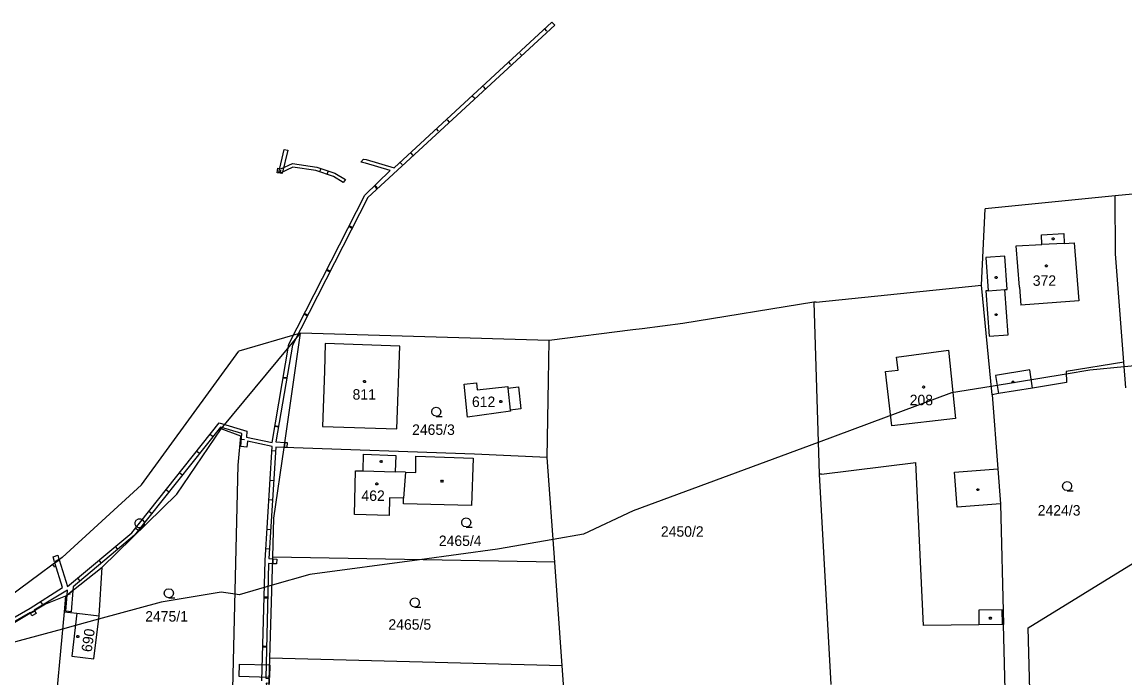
# Model space of a CAD drawing. Extents: x -760611 to -758411, y -1176479 to -1174807.
# Drawn here: x -759156.8 to -758977.4, y -1175029.4 to -1174922.6 of the extents above; entities that cross this region are included whole.
import ezdxf

# ---------------------------------------------------------------- set-up
doc = ezdxf.new("R2010")
doc.units = 0
for name, color, linetype in [('1', 7, 'Continuous'), ('11', 7, 'Continuous'), ('12', 7, 'Continuous'), ('13', 7, 'Continuous'), ('2', 7, 'Continuous'), ('3', 7, 'Continuous'), ('4', 7, 'Continuous'), ('5', 7, 'Continuous'), ('8', 7, 'Continuous')]:
    doc.layers.add(name, color=color, linetype=linetype)

msp = doc.modelspace()

# ---------------------------------------------------------------- linework, layer by layer
at = {"layer": '1'}
for p, q in [((-758953.71, -1174948.54), (-758979.01, -1174950.9)), ((-758979.01, -1174950.9), (-759000.12, -1174953.04)), ((-758978.92, -1174960.34), (-758979.01, -1174950.9)), ((-759000.75, -1174965.43), (-759000.12, -1174953.04)), ((-758977.57, -1174977.98), (-758978.92, -1174960.34)), ((-759027.66, -1174968.22), (-759000.75, -1174965.43)), ((-758999.02, -1174983.26), (-759000.75, -1174965.43)), ((-759028.01, -1174968.19), (-759049.31, -1174971.65)), ((-759028.01, -1174968.19), (-759027.14, -1174996.19)), ((-759027.66, -1174968.22), (-759028.01, -1174968.19)), ((-759049.31, -1174971.65), (-759055.94, -1174972.53)), ((-759124.45, -1174988.84), (-759111.53, -1174973.24)), ((-759111.53, -1174973.24), (-759121.55, -1174976.17)), ((-759114.2, -1174991.84), (-759111.53, -1174973.24)), ((-759071.06, -1174974.46), (-759111.53, -1174973.24)), ((-759057.44, -1174972.72), (-759071.06, -1174974.46)), ((-759055.94, -1174972.53), (-759057.44, -1174972.72)), ((-759107.51, -1174974.94), (-759107.61, -1174979.42)), ((-759095.35, -1174975.38), (-759107.51, -1174974.94)), ((-759095.86, -1174988.83), (-759095.35, -1174975.38)), ((-759071.18, -1174980.94), (-759071.06, -1174974.46)), ((-759137.42, -1174997.94), (-759121.55, -1174976.17)), ((-758977.57, -1174977.98), (-758986.97, -1174979.5)), ((-758977.24, -1174982.16), (-758977.57, -1174977.98)), ((-759107.61, -1174979.42), (-759107.95, -1174988.44)), ((-759071.42, -1174993.47), (-759071.18, -1174980.94)), ((-758986.97, -1174979.5), (-758986.89, -1174981.3)), ((-759084.91, -1174981.56), (-759082.9, -1174981.34)), ((-759084.36, -1174986.93), (-759084.91, -1174981.56)), ((-759082.9, -1174981.34), (-759082.77, -1174982.45)), ((-759082.77, -1174982.45), (-759077.83, -1174981.91)), ((-759077.83, -1174981.91), (-759077.8, -1174982.17)), ((-759077.8, -1174982.17), (-759076.06, -1174981.98)), ((-759076.06, -1174981.98), (-759075.68, -1174985.56)), ((-758992.42, -1174982.19), (-758998, -1174983.09)), ((-758986.89, -1174981.3), (-758992.42, -1174982.19)), ((-758998, -1174983.09), (-758999.02, -1174983.26)), ((-758999.02, -1174983.26), (-758998.09, -1174995.31)), ((-759077.38, -1174985.96), (-759084.36, -1174986.93)), ((-759075.68, -1174985.56), (-759077.41, -1174985.75)), ((-759077.41, -1174985.75), (-759077.38, -1174985.96)), ((-759131.66, -1174999.44), (-759124.45, -1174988.84)), ((-759121.24, -1174989.98), (-759124.45, -1174988.84)), ((-759121.67, -1174994.74), (-759121.24, -1174989.98)), ((-759107.95, -1174988.44), (-759095.86, -1174988.83)), ((-759115.85, -1175003.37), (-759114.2, -1174991.84)), ((-759083.21, -1174992.95), (-759114.2, -1174991.84)), ((-759101.36, -1174995.63), (-759101.27, -1174992.95)), ((-759101.27, -1174992.95), (-759096.01, -1174993.14)), ((-759096.01, -1174993.14), (-759096.11, -1174995.82)), ((-759092.75, -1174995.94), (-759092.75, -1174993.25)), ((-759092.75, -1174993.25), (-759083.45, -1174993.6)), ((-759083.45, -1174993.6), (-759083.74, -1175001.31)), ((-759071.42, -1174993.47), (-759083.21, -1174992.95)), ((-759070.18, -1175010.51), (-759071.42, -1174993.47)), ((-759122.62, -1175034.09), (-759121.67, -1174994.74)), ((-759026.79, -1174996.18), (-759011.4, -1174994.3)), ((-759010.16, -1175020.83), (-759011.4, -1174994.3)), ((-758998.09, -1174995.31), (-758997.64, -1175001)), ((-759102.77, -1175002.76), (-759102.56, -1174995.65)), ((-759102.56, -1174995.65), (-759101.36, -1174995.63)), ((-759094.47, -1174995.88), (-759096.11, -1174995.82)), ((-759094.47, -1174995.88), (-759092.75, -1174995.94)), ((-759026.79, -1174996.18), (-759027.14, -1174996.19)), ((-759027.14, -1174996.19), (-759025.28, -1175030.41)), ((-759150.3, -1175009.76), (-759137.42, -1174997.94)), ((-759143.8, -1175011.35), (-759131.66, -1174999.44)), ((-759097.05, -1175000.04), (-759097.13, -1175002.94)), ((-759094.76, -1175000.08), (-759097.05, -1175000.04)), ((-759094.78, -1175001), (-759094.76, -1175000.08)), ((-759083.74, -1175001.31), (-759094.78, -1175001)), ((-758997.64, -1175001), (-758997.14, -1175020.68)), ((-759116.03, -1175009.67), (-759115.85, -1175003.37)), ((-759097.13, -1175002.94), (-759102.77, -1175002.76)), ((-759150.3, -1175009.76), (-759164.6, -1175020.29)), ((-759116.51, -1175026.13), (-759116.03, -1175009.67)), ((-759070.18, -1175010.51), (-759116.03, -1175009.67)), ((-759149.75, -1175016.04), (-759143.8, -1175011.35)), ((-759144.31, -1175019.22), (-759143.8, -1175011.35)), ((-759068.96, -1175027.38), (-759070.18, -1175010.51)), ((-758993.13, -1175021.18), (-758975.38, -1175010.24)), ((-759149.75, -1175016.04), (-759153.04, -1175017.37)), ((-759149.75, -1175016.04), (-759149.99, -1175018.59)), ((-759153.04, -1175017.37), (-759165.84, -1175024.98)), ((-759149.99, -1175018.59), (-759151.16, -1175031.39)), ((-759149.99, -1175018.59), (-759147.92, -1175018.82)), ((-759147.92, -1175018.82), (-759148.74, -1175025.83)), ((-759145.14, -1175026.24), (-759144.31, -1175019.22)), ((-758997.35, -1175020.68), (-759001.17, -1175020.73)), ((-758997.14, -1175020.68), (-758997.35, -1175020.68)), ((-758995.64, -1175078.53), (-758997.14, -1175020.68)), ((-759001.17, -1175020.73), (-759010.16, -1175020.83)), ((-758991.77, -1175073.34), (-758993.13, -1175021.18)), ((-759148.74, -1175025.83), (-759145.14, -1175026.24)), ((-759116.98, -1175042.31), (-759116.51, -1175026.13)), ((-759068.96, -1175027.38), (-759116.51, -1175026.13)), ((-759067.85, -1175043.58), (-759068.96, -1175027.38))]:
    msp.add_line(p, q, dxfattribs=at)
at = {"layer": '11'}
msp.add_lwpolyline([(-758949.2, -1174976.06), (-758977.51, -1174978.74), (-758983.13, -1174979.27), (-758986.95, -1174979.9), (-758999.15, -1174981.9), (-759005.62, -1174982.97), (-759027.3, -1174991.01), (-759057.42, -1175002.17), (-759065.49, -1175005.94), (-759070.45, -1175006.82), (-759079.49, -1175008.41), (-759092.2, -1175010.11), (-759110.03, -1175012.49), (-759116.16, -1175014.27), (-759121.49, -1175015.82), (-759122.18, -1175015.72), (-759124.46, -1175015.38), (-759134.22, -1175017.02), (-759144.38, -1175019.8), (-759148.15, -1175020.83), (-759150.25, -1175021.4), (-759160.11, -1175024.09)], dxfattribs=at)
at = {"layer": '12'}
for p, q in [((-758995.08, -1174959.03), (-758990.91, -1174958.81)), ((-758994.57, -1174965.78), (-758995.08, -1174959.03)), ((-758987.29, -1174958.63), (-758990.91, -1174958.81)), ((-758987.29, -1174958.63), (-758985.65, -1174958.54)), ((-758985.65, -1174958.54), (-758984.89, -1174968)), ((-758994.57, -1174965.78), (-758994.35, -1174968.69)), ((-758984.89, -1174968), (-758994.35, -1174968.69)), ((-759107.51, -1174974.94), (-759107.61, -1174979.42)), ((-759095.35, -1174975.38), (-759107.51, -1174974.94)), ((-759095.86, -1174988.83), (-759095.35, -1174975.38)), ((-759014.55, -1174977.17), (-759006.11, -1174975.99)), ((-759014.31, -1174979.24), (-759014.55, -1174977.17)), ((-759006.11, -1174975.99), (-759004.99, -1174987.14)), ((-759016.36, -1174979.48), (-759014.31, -1174979.24)), ((-759107.61, -1174979.42), (-759107.95, -1174988.44)), ((-759015.32, -1174988.35), (-759016.36, -1174979.48)), ((-759084.91, -1174981.56), (-759082.9, -1174981.34)), ((-759084.36, -1174986.93), (-759084.91, -1174981.56)), ((-759082.9, -1174981.34), (-759082.77, -1174982.45)), ((-759082.77, -1174982.45), (-759077.83, -1174981.91)), ((-759077.83, -1174981.91), (-759077.8, -1174982.17)), ((-759077.8, -1174982.17), (-759077.41, -1174985.75)), ((-759077.38, -1174985.96), (-759084.36, -1174986.93)), ((-759077.41, -1174985.75), (-759077.38, -1174985.96)), ((-759004.99, -1174987.14), (-759015.32, -1174988.35)), ((-759107.95, -1174988.44), (-759095.86, -1174988.83)), ((-759102.77, -1175002.76), (-759102.56, -1174995.65)), ((-759102.56, -1174995.65), (-759101.36, -1174995.63)), ((-759101.36, -1174995.63), (-759096.11, -1174995.82)), ((-759094.47, -1174995.88), (-759096.11, -1174995.82)), ((-759094.47, -1174995.88), (-759094.76, -1175000.08)), ((-759097.05, -1175000.04), (-759097.13, -1175002.94)), ((-759094.76, -1175000.08), (-759097.05, -1175000.04)), ((-759097.13, -1175002.94), (-759102.77, -1175002.76)), ((-759147.92, -1175018.82), (-759148.74, -1175025.83)), ((-759147.92, -1175018.82), (-759144.31, -1175019.22)), ((-759145.14, -1175026.24), (-759144.31, -1175019.22)), ((-759148.74, -1175025.83), (-759145.14, -1175026.24))]:
    msp.add_line(p, q, dxfattribs=at)
at = {"layer": '13'}
for p, q in [((-759071.83, -1174923.74), (-759071.49, -1174924.1)), ((-759077.7, -1174929.17), (-759077.36, -1174929.53)), ((-759075.52, -1174928.08), (-759075.86, -1174927.72)), ((-759081.41, -1174933.5), (-759081.75, -1174933.13)), ((-759083.58, -1174934.6), (-759083.24, -1174934.96)), ((-759087.29, -1174938.92), (-759087.63, -1174938.55)), ((-759089.46, -1174940.02), (-759089.12, -1174940.39)), ((-759114.17, -1174943.38), (-759113.59, -1174943.48)), ((-759093.18, -1174944.34), (-759093.52, -1174943.97)), ((-759114.84, -1174947.23), (-759114.74, -1174946.74)), ((-759108.23, -1174946.43), (-759108.38, -1174946.91)), ((-759107.2, -1174947.4), (-759107.04, -1174946.93)), ((-759095.33, -1174945.45), (-759094.99, -1174945.82)), ((-759099.43, -1174949.18), (-759099.08, -1174949.54)), ((-759099.06, -1174949.76), (-759099.4, -1174949.39)), ((-759100.58, -1174951.15), (-759112.85, -1174975.22)), ((-759103.67, -1174955.86), (-759103.22, -1174956.09)), ((-759103.08, -1174956.05), (-759103.52, -1174955.82)), ((-759107.3, -1174962.99), (-759106.86, -1174963.22)), ((-759106.71, -1174963.18), (-759107.16, -1174962.95)), ((-759110.93, -1174970.12), (-759110.49, -1174970.35)), ((-759110.34, -1174970.3), (-759110.79, -1174970.08)), ((-759114.35, -1174980.4), (-759113.86, -1174980.48)), ((-759113.78, -1174980.64), (-759114.27, -1174980.56)), ((-759115.7, -1174988.29), (-759115.2, -1174988.37)), ((-759126.22, -1174989.69), (-759125.83, -1174990)), ((-759121.06, -1174989.59), (-759124.53, -1174988.55)), ((-759115.13, -1174988.53), (-759115.63, -1174988.44)), ((-759121.14, -1174990.48), (-759120.65, -1174990.53)), ((-759127.96, -1174992.85), (-759128.35, -1174992.54)), ((-759116.18, -1174992.34), (-759115.68, -1174992.37)), ((-759131.2, -1174995.95), (-759130.81, -1174996.26)), ((-759115.89, -1174997.27), (-759116.39, -1174997.24)), ((-759132.94, -1174999.11), (-759133.33, -1174998.8)), ((-759116.68, -1175000.33), (-759116.19, -1175000.36)), ((-759136.19, -1175002.21), (-759135.8, -1175002.52)), ((-759137.93, -1175005.36), (-759138.32, -1175005.05)), ((-759116.39, -1175005.25), (-759116.89, -1175005.22)), ((-759141.68, -1175007.97), (-759141.36, -1175008.35)), ((-759117.19, -1175008.31), (-759116.69, -1175008.34)), ((-759151.86, -1175010.91), (-759151.56, -1175011.31)), ((-759143.91, -1175010.65), (-759144.23, -1175010.27)), ((-759147.81, -1175013.11), (-759147.49, -1175013.49)), ((-759153.82, -1175016.94), (-759153.55, -1175017.36)), ((-759149.51, -1175015.68), (-759149.01, -1175015.72)), ((-759117.46, -1175016.3), (-759116.96, -1175016.32)), ((-759116.86, -1175016.21), (-759117.36, -1175016.2)), ((-759117.06, -1175024.21), (-759117.56, -1175024.19)), ((-759117.66, -1175024.3), (-759117.16, -1175024.31)), ((-759121.51, -1175029.13), (-759121.45, -1175027.09)), ((-759121.45, -1175027.09), (-759116.54, -1175027.23)), ((-759116.54, -1175027.23), (-759116.6, -1175029.27)), ((-759116.6, -1175029.27), (-759121.51, -1175029.13))]:
    msp.add_line(p, q, dxfattribs=at)
for points in [[(-759100.94, -1174945.57), (-759101.73, -1174945.44), (-759101.27, -1174944.91), (-759100.84, -1174944.98), (-759096.3, -1174946.35), (-759070.62, -1174922.62)], [(-759070.62, -1174922.62), (-759070.15, -1174923.14), (-759100.58, -1174951.15)], [(-759113.59, -1174943.48), (-759114.5, -1174947.24), (-759115.08, -1174947.1), (-759114.17, -1174943.38)], [(-759113.43, -1174975.02), (-759101.08, -1174950.78), (-759096.96, -1174946.79), (-759100.94, -1174945.57)], [(-759120.27, -1174989.2), (-759120.31, -1174990.16), (-759116.17, -1174991.05), (-759113.43, -1174975.02)], [(-759112.85, -1174975.22), (-759115.55, -1174990.95), (-759114.08, -1174991.04), (-759114.2, -1174991.84), (-759115.54, -1174991.78)], [(-759179.34, -1175031.74), (-759155.5, -1175018.02), (-759150.23, -1175014.64), (-759151.48, -1175010.63), (-759150.8, -1175010.13), (-759149.44, -1175014.48), (-759138.98, -1175005.71), (-759124.75, -1174987.85), (-759120.27, -1174989.2)], [(-759124.53, -1174988.55), (-759138.54, -1175006.13), (-759148.52, -1175014.54), (-759148.56, -1175015.11), (-759149.52, -1175015.86), (-759149.46, -1175015.08), (-759154.84, -1175018.31), (-759154.79, -1175018.41), (-759155.48, -1175018.82), (-759155.53, -1175018.72)], [(-759117.8, -1175029.8), (-759117.31, -1175010.26), (-759116.14, -1174991.67), (-759120.15, -1174990.8), (-759120.24, -1174991.77), (-759121.26, -1174991.7), (-759121.06, -1174989.59)], [(-759115.54, -1174991.78), (-759116.69, -1175009.91), (-759116.04, -1175009.96), (-759116.06, -1175010.76), (-759116.72, -1175010.71)], [(-759116.72, -1175010.71), (-759117.19, -1175029.4), (-759116.61, -1175029.43), (-759116.63, -1175030.23), (-759117.14, -1175030.2), (-759116.87, -1175032.24)], [(-759155.53, -1175018.72), (-759178.98, -1175032.23), (-759178.78, -1175032.57), (-759181.42, -1175034.14), (-759181.67, -1175033.72), (-759189.76, -1175039)]]:
    msp.add_lwpolyline(points, dxfattribs=at)
for points in [[(-759115.34, -1174947.13), (-759115.2, -1174946.4), (-759114.71, -1174946.49), (-759112.86, -1174945.62), (-759108.89, -1174946.21), (-759105.93, -1174947.2), (-759104.19, -1174948.25), (-759104.59, -1174948.71), (-759106.19, -1174947.74), (-759109.03, -1174946.79), (-759112.76, -1174946.24), (-759114.85, -1174947.23)], [(-759113.7, -1174991.06), (-759113.75, -1174991.86), (-759114.2, -1174991.84), (-759114.08, -1174991.04)], [(-759151.54, -1175010.46), (-759151.8, -1175009.62), (-759151.04, -1175009.38), (-759150.83, -1175010.06)], [(-759115.38, -1175010.01), (-759115.44, -1175010.8), (-759116.06, -1175010.76), (-759116.04, -1175009.96)], [(-759148.84, -1175018.57), (-759149.74, -1175018.5), (-759149.52, -1175015.86), (-759148.56, -1175015.11)], [(-759154.54, -1175018.88), (-759155.26, -1175019.25), (-759155.48, -1175018.82), (-759154.79, -1175018.41)]]:
    msp.add_lwpolyline(points, close=True, dxfattribs=at)
at = {"layer": '3'}
for points in [[(-759089.44, -1174986.76), (-759089.82, -1174986.66), (-759090.09, -1174986.39), (-759090.19, -1174986.02), (-759090.09, -1174985.65), (-759089.82, -1174985.38), (-759089.45, -1174985.28), (-759089.08, -1174985.38), (-759088.81, -1174985.65), (-759088.71, -1174986.03), (-759088.81, -1174986.41), (-759089.08, -1174986.68), (-759089.46, -1174986.78), (-759088.46, -1174986.78)], [(-758986.81, -1174998.87), (-758987.19, -1174998.77), (-758987.46, -1174998.5), (-758987.56, -1174998.13), (-758987.46, -1174997.76), (-758987.19, -1174997.49), (-758986.82, -1174997.39), (-758986.45, -1174997.49), (-758986.18, -1174997.76), (-758986.08, -1174998.14), (-758986.18, -1174998.52), (-758986.45, -1174998.79), (-758986.83, -1174998.89), (-758985.83, -1174998.89)], [(-759084.56, -1175004.78), (-759084.94, -1175004.68), (-759085.21, -1175004.41), (-759085.31, -1175004.04), (-759085.21, -1175003.67), (-759084.94, -1175003.4), (-759084.57, -1175003.3), (-759084.2, -1175003.4), (-759083.93, -1175003.67), (-759083.83, -1175004.05), (-759083.93, -1175004.43), (-759084.2, -1175004.7), (-759084.58, -1175004.8), (-759083.58, -1175004.8)], [(-759132.94, -1175016.31), (-759133.32, -1175016.21), (-759133.59, -1175015.94), (-759133.69, -1175015.57), (-759133.59, -1175015.2), (-759133.32, -1175014.93), (-759132.95, -1175014.83), (-759132.58, -1175014.93), (-759132.31, -1175015.2), (-759132.21, -1175015.58), (-759132.31, -1175015.96), (-759132.58, -1175016.23), (-759132.96, -1175016.33), (-759131.96, -1175016.33)], [(-759092.94, -1175017.82), (-759093.32, -1175017.72), (-759093.59, -1175017.45), (-759093.69, -1175017.08), (-759093.59, -1175016.71), (-759093.32, -1175016.44), (-759092.95, -1175016.34), (-759092.58, -1175016.44), (-759092.31, -1175016.71), (-759092.21, -1175017.09), (-759092.31, -1175017.47), (-759092.58, -1175017.74), (-759092.96, -1175017.84), (-759091.96, -1175017.84)]]:
    msp.add_lwpolyline(points, dxfattribs=at)
at = {"layer": '4'}
for p, q in [((-758990.99, -1174957.24), (-758987.37, -1174957.04)), ((-758990.91, -1174958.81), (-758990.99, -1174957.24)), ((-758987.37, -1174957.04), (-758987.29, -1174958.63)), ((-758995.08, -1174959.03), (-758990.91, -1174958.81)), ((-758994.57, -1174965.78), (-758995.08, -1174959.03)), ((-758987.29, -1174958.63), (-758990.91, -1174958.81)), ((-758987.29, -1174958.63), (-758985.65, -1174958.54)), ((-758985.65, -1174958.54), (-758984.89, -1174968)), ((-758996.93, -1174960.73), (-759000.05, -1174960.96)), ((-759000.05, -1174960.96), (-758999.65, -1174966.36)), ((-758996.54, -1174966.13), (-758996.93, -1174960.73)), ((-758999.65, -1174966.36), (-759000.05, -1174966.38)), ((-759000.05, -1174966.38), (-758999.5, -1174973.73)), ((-758999.65, -1174966.36), (-758996.93, -1174966.16)), ((-758996.93, -1174966.16), (-758996.54, -1174966.13)), ((-758996.39, -1174973.5), (-758996.93, -1174966.16)), ((-758994.57, -1174965.78), (-758994.35, -1174968.69)), ((-758984.89, -1174968), (-758994.35, -1174968.69)), ((-758999.5, -1174973.73), (-758996.39, -1174973.5)), ((-759014.55, -1174977.17), (-759006.11, -1174975.99)), ((-759014.31, -1174979.24), (-759014.55, -1174977.17)), ((-759006.11, -1174975.99), (-759004.99, -1174987.14)), ((-759016.36, -1174979.48), (-759014.31, -1174979.24)), ((-758992.89, -1174979.23), (-758998.47, -1174980.13)), ((-758992.42, -1174982.19), (-758992.89, -1174979.23)), ((-759015.32, -1174988.35), (-759016.36, -1174979.48)), ((-758998.47, -1174980.13), (-758998, -1174983.09)), ((-759077.8, -1174982.17), (-759077.41, -1174985.75)), ((-759004.99, -1174987.14), (-759015.32, -1174988.35)), ((-759005.16, -1174995.87), (-758998.09, -1174995.31)), ((-759101.36, -1174995.63), (-759096.11, -1174995.82)), ((-759094.47, -1174995.88), (-759094.76, -1175000.08)), ((-759004.72, -1175001.55), (-759005.16, -1174995.87)), ((-758997.64, -1175001), (-759004.72, -1175001.55)), ((-759147.92, -1175018.82), (-759144.31, -1175019.22)), ((-758997.38, -1175018.28), (-759001.2, -1175018.33)), ((-759001.2, -1175018.33), (-759001.17, -1175020.73)), ((-758997.35, -1175020.68), (-758997.38, -1175018.28))]:
    msp.add_line(p, q, dxfattribs=at)
at = {"layer": '5'}
for points in [[(-758988.99, -1174957.75), (-758988.9, -1174957.9), (-758988.99, -1174958.05), (-758989.17, -1174958.05), (-758989.26, -1174957.9), (-758989.17, -1174957.75)], [(-758990.19, -1174962.13), (-758990.09, -1174962.15), (-758990.04, -1174962.24), (-758990.02, -1174962.3), (-758990.04, -1174962.39), (-758990.12, -1174962.46), (-758990.19, -1174962.47), (-758990.28, -1174962.44), (-758990.34, -1174962.38), (-758990.36, -1174962.3), (-758990.34, -1174962.21), (-758990.26, -1174962.14)], [(-758998.27, -1174964.05), (-758998.18, -1174964.2), (-758998.27, -1174964.35), (-758998.45, -1174964.35), (-758998.54, -1174964.2), (-758998.45, -1174964.05)], [(-758998.27, -1174970.09), (-758998.18, -1174970.24), (-758998.27, -1174970.39), (-758998.45, -1174970.39), (-758998.54, -1174970.24), (-758998.45, -1174970.09)], [(-759101.11, -1174980.94), (-759101.01, -1174980.96), (-759100.96, -1174981.05), (-759100.94, -1174981.11), (-759100.96, -1174981.2), (-759101.04, -1174981.27), (-759101.11, -1174981.28), (-759101.2, -1174981.25), (-759101.26, -1174981.19), (-759101.28, -1174981.11), (-759101.26, -1174981.02), (-759101.18, -1174980.95)], [(-758995.53, -1174981.03), (-758995.44, -1174981.18), (-758995.53, -1174981.33), (-758995.71, -1174981.33), (-758995.8, -1174981.18), (-758995.71, -1174981.03)], [(-759010.16, -1174981.84), (-759010.06, -1174981.86), (-759010.01, -1174981.95), (-759009.99, -1174982.01), (-759010.01, -1174982.1), (-759010.09, -1174982.17), (-759010.16, -1174982.18), (-759010.25, -1174982.15), (-759010.31, -1174982.09), (-759010.33, -1174982.01), (-759010.31, -1174981.92), (-759010.23, -1174981.85)], [(-759078.94, -1174984.2), (-759078.84, -1174984.22), (-759078.79, -1174984.31), (-759078.77, -1174984.37), (-759078.79, -1174984.46), (-759078.87, -1174984.53), (-759078.94, -1174984.54), (-759079.03, -1174984.51), (-759079.09, -1174984.45), (-759079.11, -1174984.37), (-759079.09, -1174984.28), (-759079.01, -1174984.21)], [(-759098.33, -1174993.98), (-759098.24, -1174994.13), (-759098.33, -1174994.28), (-759098.51, -1174994.28), (-759098.6, -1174994.13), (-759098.51, -1174993.98)], [(-759088.41, -1174997.19), (-759088.32, -1174997.34), (-759088.41, -1174997.49), (-759088.59, -1174997.49), (-759088.68, -1174997.34), (-759088.59, -1174997.19)], [(-759099.11, -1174997.61), (-759099.01, -1174997.63), (-759098.96, -1174997.72), (-759098.94, -1174997.78), (-759098.96, -1174997.87), (-759099.04, -1174997.94), (-759099.11, -1174997.95), (-759099.2, -1174997.92), (-759099.26, -1174997.86), (-759099.28, -1174997.78), (-759099.26, -1174997.69), (-759099.18, -1174997.62)], [(-759001.24, -1174998.55), (-759001.15, -1174998.7), (-759001.24, -1174998.85), (-759001.42, -1174998.85), (-759001.51, -1174998.7), (-759001.42, -1174998.55)], [(-758999.2, -1175019.48), (-758999.11, -1175019.63), (-758999.2, -1175019.78), (-758999.38, -1175019.78), (-758999.47, -1175019.63), (-758999.38, -1175019.48)], [(-759147.77, -1175022.44), (-759147.67, -1175022.46), (-759147.62, -1175022.55), (-759147.6, -1175022.61), (-759147.62, -1175022.7), (-759147.7, -1175022.77), (-759147.77, -1175022.78), (-759147.86, -1175022.75), (-759147.92, -1175022.69), (-759147.94, -1175022.61), (-759147.92, -1175022.52), (-759147.84, -1175022.45)]]:
    msp.add_lwpolyline(points, close=True, dxfattribs=at)
at = {"layer": '8'}
msp.add_line((-759137.76, -1175004.19), (-759137.66, -1175004.19), dxfattribs=at)
msp.add_lwpolyline([(-759137.52, -1175003.47), (-759137.18, -1175003.66), (-759136.99, -1175004), (-759136.99, -1175004.39), (-759137.18, -1175004.73), (-759137.52, -1175004.92), (-759137.91, -1175004.92), (-759138.25, -1175004.73), (-759138.44, -1175004.39), (-759138.44, -1175004), (-759138.25, -1175003.66), (-759137.91, -1175003.47)], close=True, dxfattribs=at)

# ---------------------------------------------------------------- texts
at = {"layer": '2'}
for s, p in [('372', (-758992.4, -1174965.54)), ('811', (-759103.06, -1174984.06)), ('612', (-759083.64, -1174985.26)), ('208', (-759012.42, -1174984.97)), ('2465/3', (-759093.38, -1174989.8)), ('462', (-759101.62, -1175000.54)), ('2424/3', (-758991.59, -1175002.93)), ('2465/4', (-759089.03, -1175007.88)), ('2450/2', (-759052.9, -1175006.37)), ('2475/1', (-759136.8, -1175020.18)), ('2465/5', (-759097.23, -1175021.5))]:
    msp.add_text(s, height=1.7, dxfattribs=at).set_placement(p)
msp.add_text('690', height=1.7, rotation=81.6465, dxfattribs=at).set_placement((-759145.53, -1175025.22))

doc.saveas('drawing.dxf')
